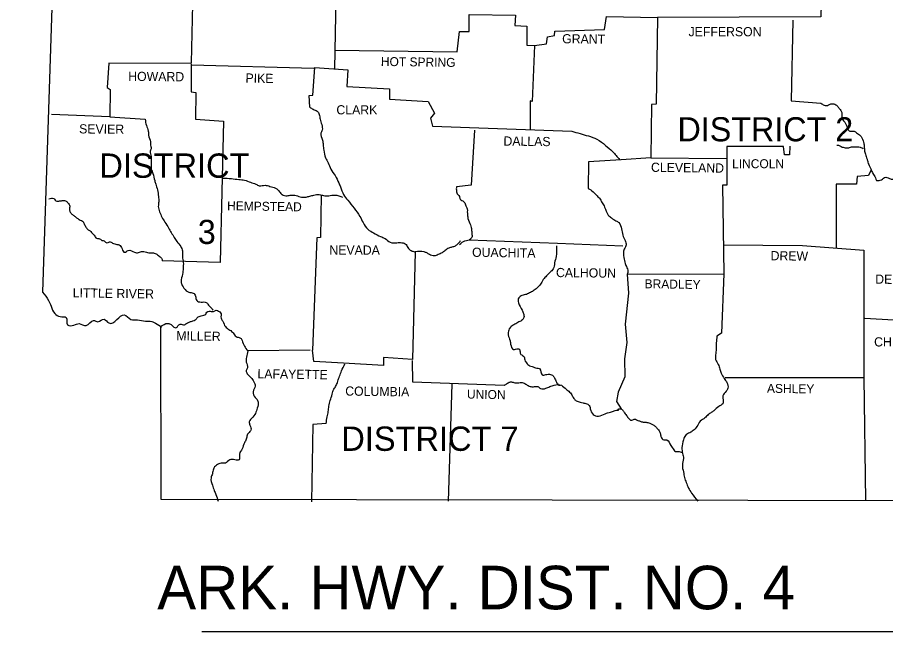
# Model space of a CAD drawing. Extents: x 21307 to 29830, y 1322443 to 1332359.
# Drawn here: x 24969 to 25700, y 1330373 to 1330891 of the extents above; entities that cross this region are included whole.
import ezdxf

# ---------------------------------------------------------------- set-up
doc = ezdxf.new("R2010")
doc.units = 0
doc.layers.add('R_Draft', color=7, linetype='Continuous')

msp = doc.modelspace()

# ---------------------------------------------------------------- linework, layer by layer
at = {"layer": 'R_Draft'}
for p, q in [((25238.04, 1330960.83), (25235.94, 1330847.79)), ((25124.1, 1330373.35), (25718.2, 1330373.35))]:
    msp.add_line(p, q, dxfattribs=at)
for points in [[(24968.58, 1331447.01), (25005.84, 1331147.85), (24989.64, 1330659.51)], [(25117.05, 1330939.63), (25115.11, 1330852.83)], [(25714.32, 1330912.05), (25646.28, 1330913.85), (25645.92, 1330891.71), (25508.22, 1330891.17)], [(25236.24, 1330863.63), (25339.2, 1330862.19), (25341.18, 1330879.29), (25349.28, 1330879.29), (25349.46, 1330893.69), (25388.34, 1330893.15), (25387.98, 1330884.51), (25398.06, 1330883.79), (25398.06, 1330867.95), (25404.54, 1330867.41), (25404.46, 1330865.76)], [(25404.54, 1330867.41), (25414.62, 1330868.85), (25415.34, 1330874.97), (25421.28, 1330876.05), (25421.64, 1330879.65), (25463.58, 1330880.91), (25465.2, 1330891.89), (25508.22, 1330891.17)], [(25508.22, 1330891.17), (25507.14, 1330818.09), (25503, 1330817.91), (25502.46, 1330772.73)], [(25622.34, 1330888.83), (25620.9, 1330820.97), (25645.92, 1330818.99)], [(25404.54, 1330867.41), (25402.38, 1330820.25), (25400.76, 1330820.79), (25400.94, 1330796.31)], [(25114.92, 1330852.47), (25045.8, 1330852.65), (25044.18, 1330832.13), (25046.7, 1330830.33), (25046.52, 1330807.29), (24997.38, 1330809.45)], [(25115.1, 1330852.47), (25115.1, 1330828.53), (25119.06, 1330827.81), (25118.7, 1330805.49), (25142.46, 1330803.69), (25139.58, 1330684.71), (25090.62, 1330685.97)], [(25115.46, 1330851.21), (25218.42, 1330848.51)], [(25215, 1330815.57), (25214.64, 1330825.47), (25217.52, 1330825.65), (25219.32, 1330848.87), (25247.04, 1330847.07), (25246.32, 1330832.85), (25282.14, 1330830.87), (25282.32, 1330822.23), (25314.72, 1330820.25), (25320.3, 1330810.53), (25316.88, 1330806.21), (25318.5, 1330799.55), (25435.86, 1330795.23)], [(25046.52, 1330807.29), (25076.4, 1330805.49)], [(25353.78, 1330796.13), (25351.08, 1330749.87), (25338.66, 1330748.43)], [(25619.58, 1330782.57), (25619.28, 1330775.25), (25615.14, 1330775.25), (25614.42, 1330782.27), (25566.54, 1330782.27), (25566.59, 1330772.37)], [(25477.56, 1330771.19), (25449.9, 1330769.49), (25449.72, 1330746.99)], [(25502.46, 1330772.73), (25477.56, 1330771.19)], [(25502.46, 1330772.73), (25566.18, 1330772.37)], [(25566.59, 1330772.37), (25566.72, 1330749.87), (25562.94, 1330749.69), (25564.02, 1330674.99)], [(25688.22, 1330762.83), (25686.06, 1330757.97), (25676.52, 1330757.07), (25675.98, 1330750.59), (25658.88, 1330750.59), (25658.7, 1330696.77)], [(25224.54, 1330741.59), (25224.18, 1330705.77), (25220.94, 1330705.41), (25217.34, 1330610.55)], [(25349.28, 1330703.61), (25423.8, 1330700.91), (25479.06, 1330698.75)], [(25563.48, 1330699.47), (25630.26, 1330698.93), (25682.1, 1330694.97)], [(25303.92, 1330693.53), (25301.58, 1330602.81), (25277.28, 1330604.43), (25277.1, 1330597.77), (25243.49, 1330599.73)], [(25682.1, 1330694.97), (25682.1, 1330587.33), (25683.54, 1330483.83)], [(25482.66, 1330674.81), (25483.68, 1330658.78), (25481.03, 1330632.72), (25482.17, 1330617.23), (25480.28, 1330603.26), (25480.66, 1330588.15), (25474.99, 1330575.31), (25473.48, 1330567.37), (25477.64, 1330561.33)], [(25482.66, 1330674.81), (25564.02, 1330674.99)], [(25564.02, 1330674.99), (25562.22, 1330624.95), (25558.26, 1330622.43)], [(25683, 1330637.55), (25707.12, 1330636.11), (25708.2, 1330625.67), (25729.98, 1330626.39), (25730.88, 1330635.21), (25735.02, 1330635.21)], [(25089.18, 1330630.53), (25089.54, 1330484.91), (25749.24, 1330483.83)], [(25215.33, 1330610.53), (25162.8, 1330610.01)], [(25243.49, 1330599.74), (25218.6, 1330601.19), (25217.34, 1330610.55)], [(25378.8, 1330580.85), (25301.94, 1330583.73), (25301.58, 1330601.91)], [(25565.1, 1330587.51), (25682.1, 1330587.51)], [(25334.7, 1330582.11), (25331.82, 1330483.29)], [(25228.86, 1330548.81), (25217.7, 1330548.09), (25216.44, 1330482.75)]]:
    msp.add_lwpolyline(points, dxfattribs=at)
for points in [[(25215, 1330815.57), (25217.88, 1330813.77), (25221.3, 1330812.15), (25223.1, 1330809.45), (25223.82, 1330805.31), (25225.08, 1330800.81), (25225.44, 1330796.13), (25224.36, 1330793.61), (25225.8, 1330787.85), (25226.34, 1330783.89), (25226.88, 1330779.21), (25228.32, 1330772.91), (25230.66, 1330768.59), (25232.82, 1330763.37), (25236.42, 1330757.79), (25239.48, 1330751.67), (25240.92, 1330748.43), (25243.62, 1330741.77), (25247.04, 1330737.27), (25252.44, 1330730.43), (25257.3, 1330723.41), (25260, 1330718.19), (25264.14, 1330712.43), (25268.82, 1330709.55), (25274.76, 1330706.49), (25278.54, 1330704.69), (25282.86, 1330701.63), (25288.44, 1330701.27), (25292.58, 1330701.27), (25296.36, 1330699.65), (25298.16, 1330696.41), (25301.4, 1330694.25), (25303.92, 1330693.53)], [(25645.92, 1330818.99), (25648.62, 1330817.19), (25652.4, 1330817.37), (25654.92, 1330818.45), (25656.9, 1330818.27), (25659.6, 1330816.65), (25661.4, 1330814.49), (25662.66, 1330812.87), (25663.56, 1330810.35), (25663.56, 1330808.01), (25664.46, 1330804.77), (25665.54, 1330803.51), (25666.98, 1330801.17), (25667.88, 1330799.01), (25668.42, 1330797.57), (25670.4, 1330795.23), (25672.2, 1330795.41), (25673.82, 1330795.23), (25675.98, 1330793.97), (25679.22, 1330791.45), (25679.76, 1330790.73), (25681.92, 1330786.05), (25682.28, 1330783.17), (25682.64, 1330779.39), (25683.36, 1330775.79), (25684.8, 1330771.83), (25685.52, 1330769.13), (25687.14, 1330765.35), (25688.22, 1330762.83), (25689.66, 1330759.59), (25691.82, 1330755.99), (25692.72, 1330753.83), (25695.78, 1330754.01), (25697.94, 1330754.91), (25699.56, 1330756.35), (25701.54, 1330756.17), (25703.7, 1330755.45), (25706.58, 1330754.91), (25708.38, 1330755.99), (25709.28, 1330756.71), (25709.46, 1330758.33), (25711.08, 1330759.23), (25712.88, 1330757.97), (25714.86, 1330755.09), (25714.86, 1330753.29), (25714.14, 1330752.21), (25711.8, 1330750.77), (25708.56, 1330749.69), (25707.66, 1330748.43), (25710.72, 1330746.99), (25715.58, 1330746.63), (25716.84, 1330747.71), (25720.08, 1330746.81), (25721.34, 1330747.71), (25725.66, 1330747.53), (25727.64, 1330748.97), (25731.6, 1330748.79), (25732.86, 1330747.89), (25732.86, 1330746.27), (25736.1, 1330745.55), (25738.44, 1330746.09), (25741.5, 1330745.19), (25744.2, 1330743.75), (25745.64, 1330741.77), (25747.44, 1330739.61), (25749.06, 1330740.15), (25750.32, 1330741.77), (25753.02, 1330744.65), (25753.02, 1330746.45), (25753.74, 1330747.71), (25754.64, 1330749.51)], [(25076.4, 1330805.49), (25077.3, 1330800.09), (25078.92, 1330795.41), (25079.1, 1330791.81), (25080.72, 1330786.41), (25080.72, 1330784.43), (25081.26, 1330780.47), (25080.54, 1330778.31), (25081.44, 1330773.99), (25081.26, 1330770.75), (25081.26, 1330768.05), (25081.44, 1330763.55), (25082.88, 1330759.59), (25084.32, 1330753.65), (25085.22, 1330750.59), (25086.66, 1330745.91), (25087.56, 1330740.15), (25087.74, 1330735.83), (25087.38, 1330731.87), (25088.46, 1330727.37), (25090.44, 1330722.87), (25092.96, 1330718.55), (25096.02, 1330713.69), (25098.18, 1330709.91), (25100.88, 1330705.77), (25103.04, 1330702.35), (25106.28, 1330698.03), (25107.72, 1330694.43), (25107.72, 1330689.39), (25108.44, 1330684.71), (25108.26, 1330679.49), (25107.9, 1330674.81), (25106.64, 1330668.33), (25107.54, 1330665.27), (25110.96, 1330660.77), (25113.12, 1330659.51), (25116.9, 1330658.79), (25118.7, 1330656.27), (25119.78, 1330652.49), (25123.56, 1330651.23), (25127.7, 1330650.87), (25129.68, 1330648.71), (25132.38, 1330645.83), (25133.28, 1330644.39)], [(25435.86, 1330795.23), (25449.9, 1330791.27), (25457.1, 1330788.57), (25464.3, 1330783.35), (25470.24, 1330778.13), (25476.18, 1330771.47)], [(25659.24, 1330783.54), (25659.6, 1330783.53), (25661.94, 1330782.99), (25663.92, 1330781.91), (25665.36, 1330781.55), (25667.52, 1330781.19), (25669.32, 1330781.37), (25672.38, 1330782.09), (25674.18, 1330782.09), (25677.06, 1330782.09), (25678.86, 1330781.91), (25681.56, 1330780.47)], [(25142.1, 1330755.81), (25148.94, 1330755.27), (25155.24, 1330754.55), (25160.1, 1330754.01), (25165.14, 1330752.21), (25169.64, 1330750.59), (25172.52, 1330749.33), (25177.38, 1330749.69), (25181.52, 1330748.79), (25186.2, 1330747.17), (25189.62, 1330744.11), (25191.78, 1330741.77), (25195.92, 1330740.87), (25199.34, 1330741.41), (25203.48, 1330741.05), (25208.16, 1330739.61), (25211.94, 1330739.79), (25215, 1330740.51), (25218.6, 1330741.41), (25223.1, 1330741.77), (25226.52, 1330741.05), (25231.02, 1330740.87), (25236.24, 1330741.41), (25242.72, 1330739.61)], [(25338.66, 1330748.43), (25338.66, 1330745.01), (25339.92, 1330741.77), (25341.18, 1330740.33), (25341.72, 1330737.99), (25343.34, 1330736.91), (25345.68, 1330734.75), (25346.94, 1330731.69), (25347.84, 1330729.71), (25347.84, 1330727.19), (25348.02, 1330724.67), (25348.38, 1330721.61), (25350.54, 1330716.21), (25351.08, 1330714.05), (25351.44, 1330712.25), (25351.62, 1330709.19), (25351.62, 1330705.59), (25349.28, 1330703.61)], [(25449.72, 1330746.99), (25453.86, 1330744.29), (25457.28, 1330740.69), (25459.8, 1330737.99), (25461.42, 1330734.93), (25463.58, 1330731.33), (25466.64, 1330724.49), (25469.34, 1330722.15), (25473.12, 1330719.81), (25475.46, 1330718.19), (25477.8, 1330712.97), (25478.88, 1330707.75), (25480.86, 1330703.07), (25481.76, 1330699.47), (25480.14, 1330695.87), (25479.78, 1330688.67), (25480.86, 1330683.81), (25482.3, 1330680.21), (25483.2, 1330676.07), (25482.66, 1330674.81)], [(24995.22, 1330738.35), (24999.18, 1330738.53), (25001.88, 1330736.19), (25003.5, 1330736.37), (25006.38, 1330736.73), (25009.08, 1330736.55), (25011.06, 1330734.93), (25012.68, 1330732.05), (25012.5, 1330729.35), (25012.68, 1330728.27), (25013.94, 1330725.93), (25016.1, 1330724.13), (25018.44, 1330722.33), (25020.6, 1330720.89), (25024.2, 1330718.55), (25024.56, 1330717.83), (25026, 1330714.95), (25027.8, 1330712.61), (25029.96, 1330711.17), (25032.3, 1330708.65), (25033.38, 1330707.57), (25035.18, 1330705.05), (25037.16, 1330704.87), (25039.86, 1330703.25), (25041.84, 1330702.71), (25044, 1330701.27), (25046.16, 1330701.99), (25048.86, 1330700.91), (25052.46, 1330699.83), (25054.44, 1330699.47), (25056.78, 1330696.05), (25059.12, 1330693.17), (25062, 1330694.79), (25067.4, 1330693.17), (25070.82, 1330692.99), (25073.88, 1330693.89), (25076.22, 1330693.71), (25080.54, 1330692.63), (25083.24, 1330692.63), (25086.12, 1330691.55), (25088.82, 1330689.39), (25090.62, 1330687.05), (25090.62, 1330685.97)], [(25341.9, 1330702.71), (25339.92, 1330700.37), (25337.58, 1330698.39), (25334.88, 1330697.49), (25332.36, 1330696.77), (25329.12, 1330694.61), (25326.6, 1330692.81), (25323.18, 1330691.19), (25319.94, 1330690.11), (25315.98, 1330691.37), (25313.82, 1330692.63), (25311.48, 1330693.53), (25303.92, 1330693.53)], [(25341.18, 1330699.83), (25345.86, 1330702.89), (25351.08, 1330703.61)], [(25423.08, 1330698.75), (25422.72, 1330689.75), (25421.46, 1330684.17), (25420.2, 1330679.13), (25417.5, 1330676.25), (25414.62, 1330673.37), (25411.92, 1330670.13), (25409.58, 1330666.17), (25407.24, 1330663.65), (25404.18, 1330661.13), (25401.12, 1330659.33), (25397.7, 1330657.71), (25393.92, 1330656.81), (25391.22, 1330654.83), (25391.04, 1330650.51), (25394.1, 1330644.39), (25395.18, 1330641.51), (25395.54, 1330638.09), (25394.28, 1330636.11), (25391.4, 1330634.49), (25387.98, 1330632.51), (25384.92, 1330630.71), (25382.76, 1330627.65), (25382.4, 1330623.51), (25383.84, 1330618.65), (25384.38, 1330615.77), (25386.72, 1330611.27), (25388.52, 1330611.45), (25391.76, 1330611.27), (25392.12, 1330610.37), (25392.3, 1330609.47), (25393.02, 1330607.13), (25395.72, 1330605.15), (25396.08, 1330603.35), (25397.7, 1330599.93), (25400.4, 1330597.59), (25402.38, 1330596.87), (25406.52, 1330595.61), (25408.68, 1330595.07), (25411.02, 1330589.85), (25413.9, 1330590.03), (25416.06, 1330590.39), (25419.66, 1330589.49), (25421.28, 1330587.33), (25422.9, 1330583.73), (25425.06, 1330581.21), (25426.5, 1330581.21)], [(24989.64, 1330659.51), (24994.86, 1330652.67), (24997.02, 1330647.81), (25000.08, 1330641.51), (25004.58, 1330638.99), (25009.8, 1330638.09), (25010.88, 1330631.97), (25016.28, 1330631.79), (25020.6, 1330633.05), (25026.54, 1330631.43), (25032.84, 1330635.75), (25036.44, 1330634.67), (25041.66, 1330636.83), (25045.62, 1330633.59), (25052.46, 1330636.47), (25058.58, 1330640.43), (25064.34, 1330636.65), (25069.92, 1330636.11), (25076.58, 1330635.21), (25081.8, 1330634.85), (25086.48, 1330632.51), (25089.9, 1330630.17), (25089.18, 1330630.53)], [(25089.18, 1330630.53), (25095.48, 1330633.23), (25098.18, 1330632.33), (25100.52, 1330629.99), (25103.22, 1330629.99), (25104.66, 1330632.15), (25107.36, 1330632.33), (25109.52, 1330632.15), (25111.86, 1330633.59), (25113.84, 1330634.49), (25116.54, 1330635.39), (25118.52, 1330636.11), (25120.32, 1330638.09), (25123.56, 1330639.71), (25127.34, 1330640.97), (25128.42, 1330642.77), (25130.22, 1330643.49), (25133.82, 1330643.31), (25136.16, 1330644.39), (25138.14, 1330643.49), (25139.94, 1330642.23), (25140.3, 1330637.55), (25141.74, 1330635.03), (25143.9, 1330630.53), (25146.96, 1330628.19), (25149.84, 1330625.85), (25150.92, 1330624.41), (25153.98, 1330621.71), (25156.68, 1330620.81), (25157.94, 1330618.83), (25159.92, 1330614.15), (25162.8, 1330610.01)], [(25558.26, 1330622.43), (25557.72, 1330616.85), (25557.54, 1330611.63), (25557.18, 1330606.59), (25557.18, 1330602.81), (25559.34, 1330598.67), (25560.6, 1330594.71), (25561.86, 1330591.29), (25564.38, 1330586.79), (25566.72, 1330583.37), (25567.44, 1330578.51), (25566, 1330575.99), (25563.3, 1330572.21), (25563.12, 1330565.37), (25559.88, 1330563.21), (25555.74, 1330559.61), (25553.4, 1330557.99), (25550.88, 1330556.37), (25548.18, 1330553.49), (25544.22, 1330550.79), (25541.34, 1330546.29), (25538.1, 1330542.87), (25535.4, 1330541.07), (25531.62, 1330538.73), (25530, 1330535.13), (25528.74, 1330528.47), (25529.28, 1330523.61), (25530, 1330519.29), (25529.1, 1330513.89), (25530, 1330507.95), (25530.9, 1330503.27), (25532.34, 1330499.13), (25534.32, 1330494.45), (25536.84, 1330490.13), (25542.24, 1330483.47)], [(25162.8, 1330610.01), (25161.72, 1330604.79), (25161.54, 1330600.65), (25162.44, 1330595.79), (25161.54, 1330593.45), (25162.98, 1330590.03), (25165.68, 1330587.33), (25167.66, 1330584.45), (25168.92, 1330580.31), (25167.3, 1330575.63), (25169.1, 1330570.77), (25170.72, 1330568.97), (25171.62, 1330566.09), (25170.36, 1330560.51), (25168.74, 1330556.37), (25165.14, 1330552.23), (25164.06, 1330550.25), (25164.6, 1330547.55), (25165.5, 1330543.23), (25164.6, 1330541.97), (25162.26, 1330538.91), (25161.54, 1330535.49), (25159.92, 1330532.61), (25158.12, 1330527.39), (25155.78, 1330523.07), (25155.42, 1330518.21), (25151.82, 1330518.21), (25147.68, 1330518.21), (25143.9, 1330515.51), (25140.48, 1330515.33), (25136.34, 1330513.71), (25133.82, 1330510.29), (25132.92, 1330506.51), (25131.84, 1330502.91), (25132.92, 1330496.79), (25134.54, 1330492.47), (25135.8, 1330489.05), (25137.96, 1330483.47)], [(25228.86, 1330548.81), (25229.76, 1330554.57), (25230.66, 1330559.07), (25231.2, 1330563.39), (25232.28, 1330568.25), (25233.9, 1330573.47), (25235.34, 1330577.79), (25237.32, 1330580.85), (25238.58, 1330584.45), (25240.2, 1330588.77), (25241.82, 1330593.27), (25244.7, 1330599.03)], [(25378.8, 1330580.85), (25381.68, 1330582.83), (25384.38, 1330583.91), (25387.08, 1330583.37), (25389.96, 1330583.01), (25392.48, 1330583.37), (25395.72, 1330582.83), (25398.42, 1330581.21), (25401.48, 1330579.95), (25404.54, 1330579.95), (25407.24, 1330579.95), (25409.58, 1330578.33), (25413.9, 1330578.51), (25417.5, 1330579.95), (25421.1, 1330581.03), (25425.96, 1330581.57), (25430.28, 1330578.51), (25433.34, 1330575.99), (25435.86, 1330573.11), (25437.66, 1330569.87), (25439.64, 1330568.07), (25442.88, 1330566.81), (25445.4, 1330566.27), (25448.46, 1330565.37), (25450.08, 1330564.65), (25451.52, 1330561.23), (25453.86, 1330556.55), (25458.36, 1330554.93), (25463.94, 1330557.09), (25468.44, 1330558.35), (25471.68, 1330559.43), (25473.66, 1330560.15), (25475.46, 1330560.33), (25474.92, 1330560.69), (25477.08, 1330561.23), (25479.06, 1330559.79), (25480.32, 1330557.81), (25482.48, 1330554.93), (25484.46, 1330552.41), (25486.44, 1330551.51), (25488.42, 1330552.59), (25491.12, 1330551.69), (25493.46, 1330550.79), (25496.16, 1330550.07), (25498.5, 1330549.89), (25501.56, 1330549.17), (25503.9, 1330547.91), (25506.06, 1330546.65), (25508.22, 1330544.31), (25510.38, 1330540.71), (25511.1, 1330537.83), (25513.62, 1330534.95), (25515.96, 1330534.95), (25519.38, 1330530.27), (25520.64, 1330528.47), (25523.34, 1330525.23), (25525.32, 1330525.23), (25529.1, 1330524.51)]]:
    msp.add_spline(points, degree=3, dxfattribs=at)

# ---------------------------------------------------------------- texts
for s, height, p in [('JEFFERSON', 7.74, (25534.32, 1330875.33)), ('CLARK', 7.74, (25237.5, 1330809.45)), ('DISTRICT 2', 20.339, (25525.03, 1330786.75)), ('DISTRICT', 20.52, (25037.7, 1330755.99)), ('LINCOLN', 7.56, (25571.04, 1330764.09)), ('3', 20.34, (25120.68, 1330700.19)), ('NEVADA', 7.74, (25231.56, 1330691.19)), ('CHICOT', 7.74, (25690.74, 1330613.79)), ('DISTRICT 7', 20.52, (25241.64, 1330525.77)), ('  ARK. HWY. DIST. NO. 4', 36.72, (25059.23, 1330392.17))]:
    msp.add_text(s, height=height, dxfattribs=at).set_placement(p)
for s, height, rotation, p in [('GRANT', 7.741, 359.40319, (25427.76, 1330869.39)), ('HOT SPRING', 7.561, 359.22157, (25274.94, 1330850.31)), ('HOWARD', 7.741, 359.51446, (25062, 1330837.71)), ('PIKE', 7.739, 359.04516, (25160.82, 1330836.27)), ('SEVIER', 7.741, 359.42706, (25020.6, 1330793.43)), ('DALLAS', 7.739, 359.24615, (25378.26, 1330783.17)), ('CLEVELAND', 7.741, 359.33765, (25502.64, 1330761.03)), ('HEMPSTEAD', 7.559, 359.1885, (25145.34, 1330728.63)), ('OUACHITA', 7.741, 359.20428, (25351.8, 1330689.39)), ('DREW', 7.739, 359.22578, (25603.44, 1330686.51)), ('CALHOUN', 7.741, 359.36341, (25422.54, 1330672.29)), ('BRADLEY', 7.559, 359.1449, (25497.24, 1330662.93)), ('DESHA', 7.739, 359.3704, (25691.64, 1330666.71)), ('LITTLE RIVER', 7.7412, 359.16968, (25015.2, 1330655.19)), ('MILLER', 7.739, 359.13195, (25102.5, 1330619.01)), ('LAFAYETTE', 7.739, 359.18387, (25170.9, 1330586.97)), ('COLUMBIA', 7.739, 359.21248, (25244.88, 1330572.39)), ('ASHLEY', 7.561, 359.2361, (25600.38, 1330574.73)), ('UNION', 7.561, 358.95837, (25347.48, 1330569.87))]:
    msp.add_text(s, height=height, rotation=rotation, dxfattribs=at).set_placement(p)

doc.saveas('drawing.dxf')
